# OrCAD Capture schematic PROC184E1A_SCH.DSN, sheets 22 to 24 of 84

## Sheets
22 22. SOC DEBUG: size C; title: DEBUG; note: PROC184_SCH
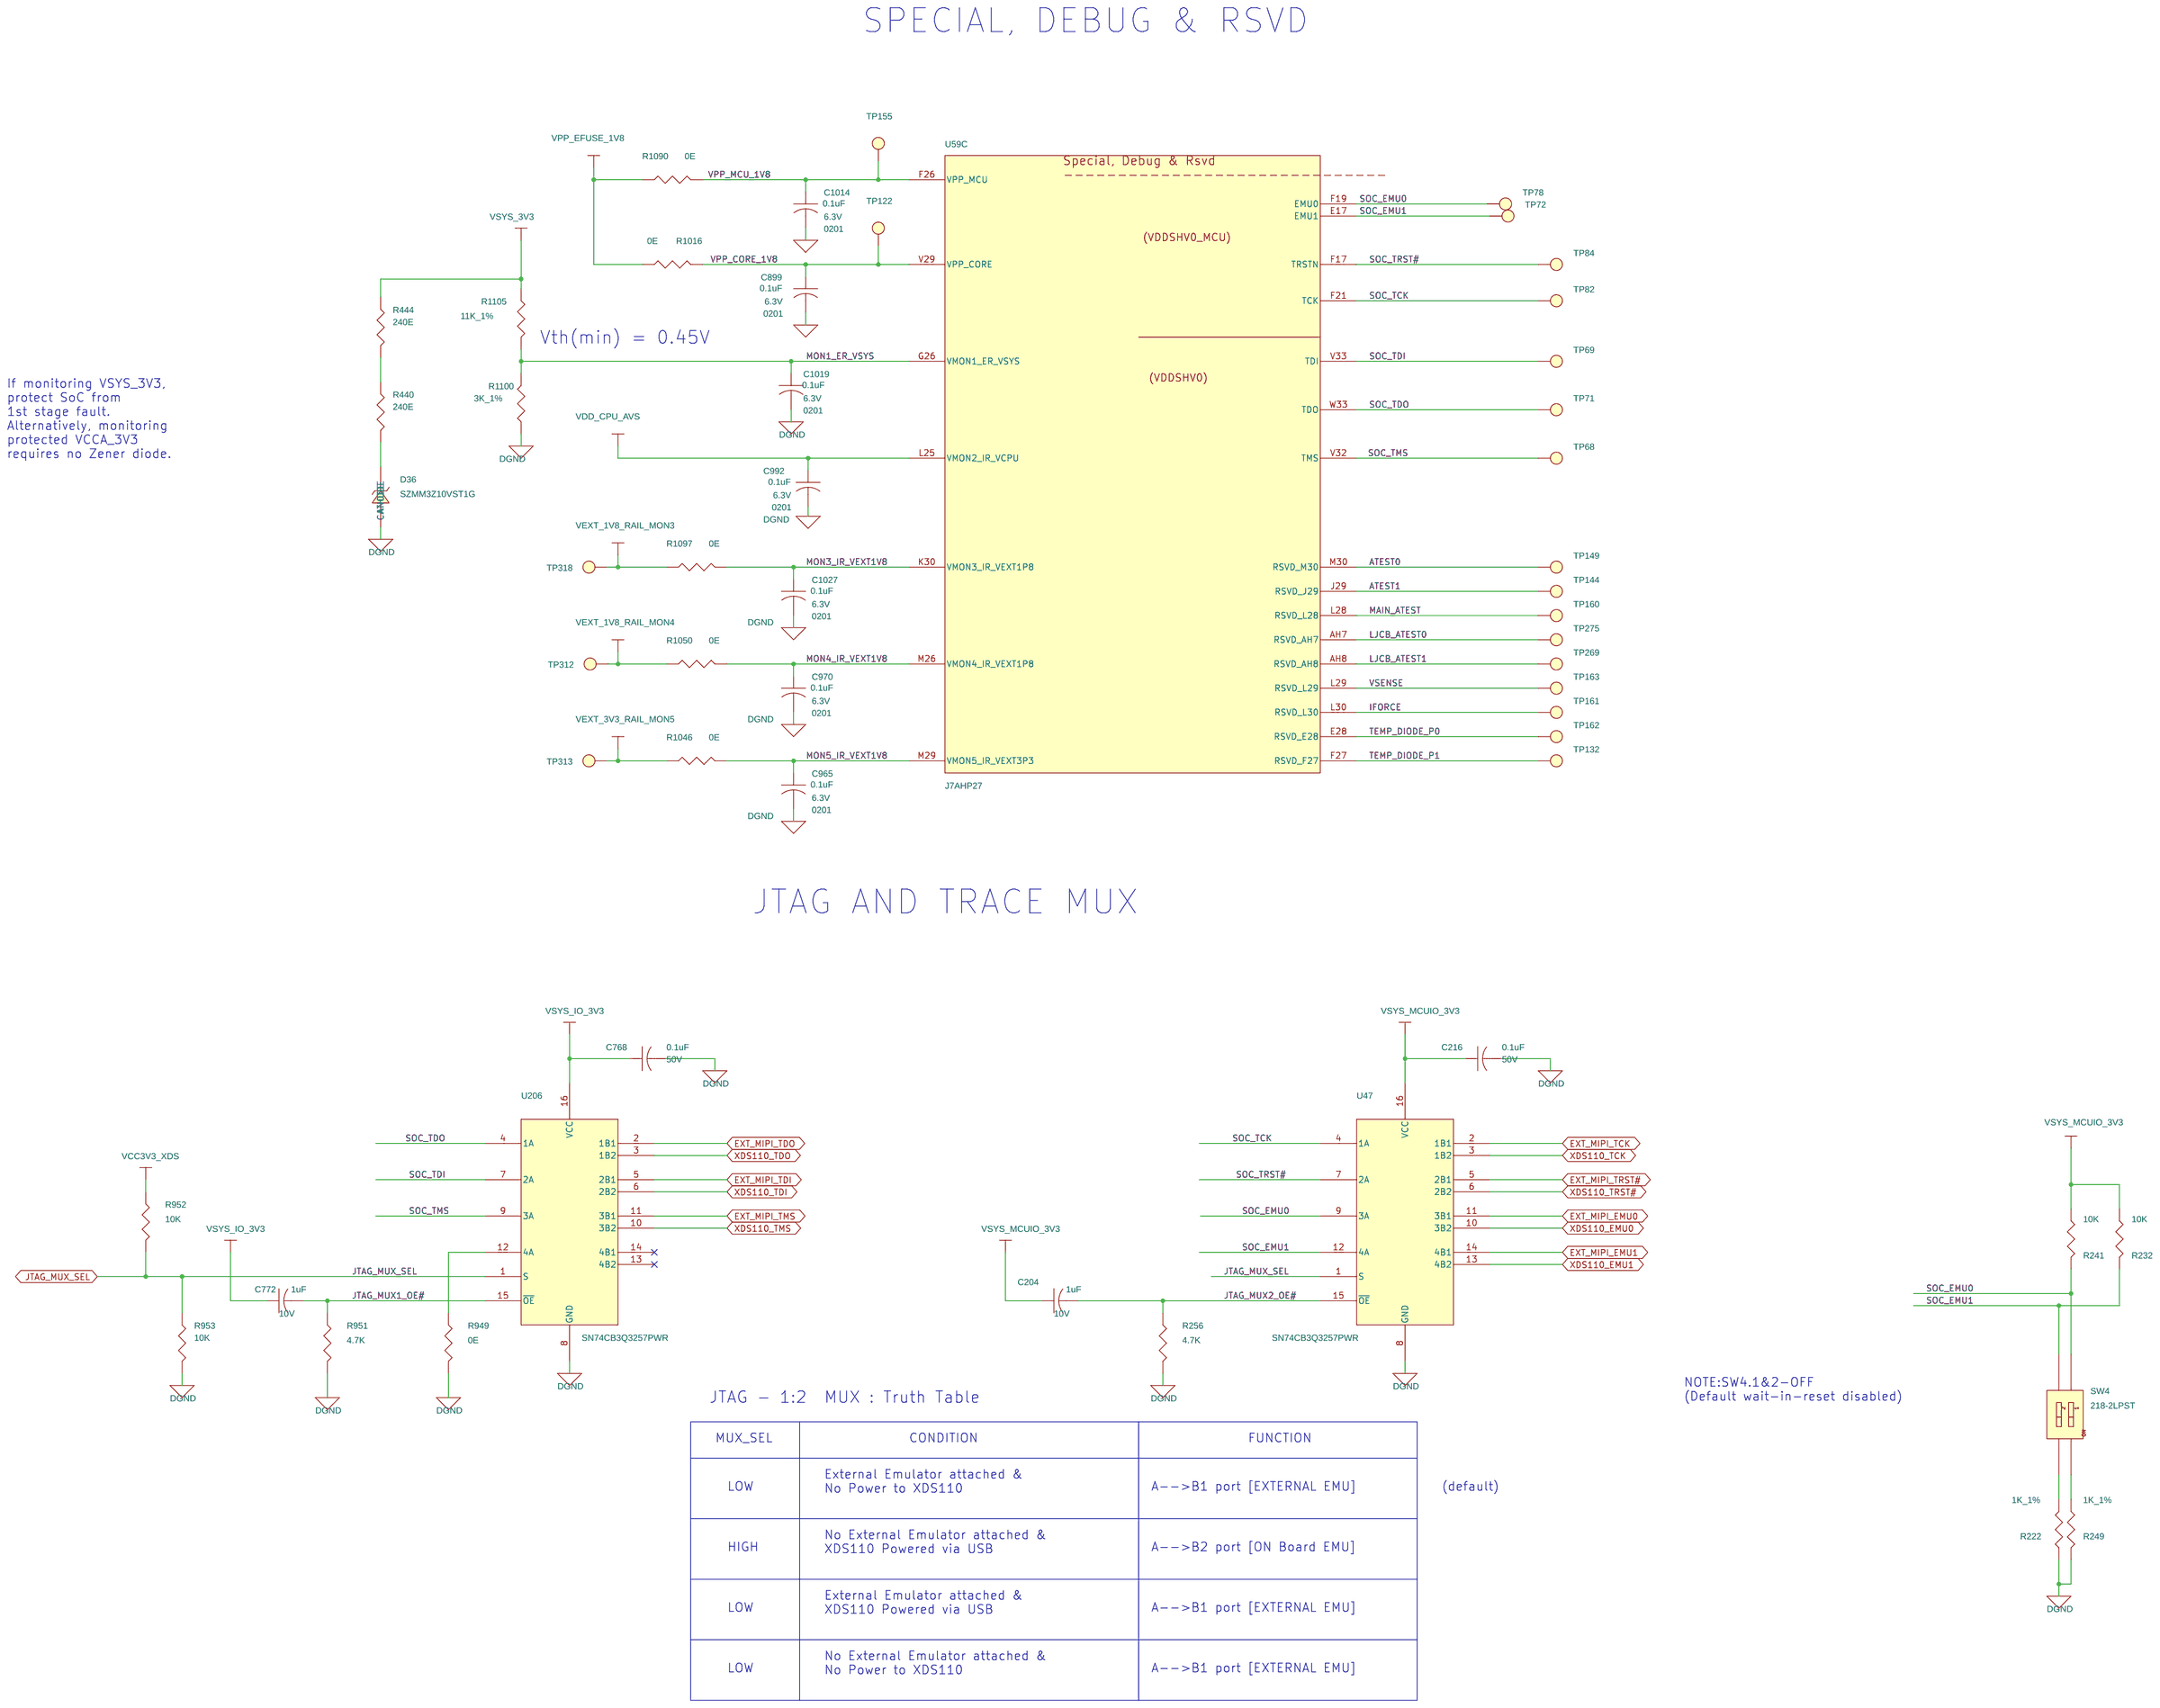
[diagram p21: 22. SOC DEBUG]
23 76.PMIC SUPPORT CRT: size C; title: PMIC SUPPORT CIRCUITRY; note: PROC184_SCH
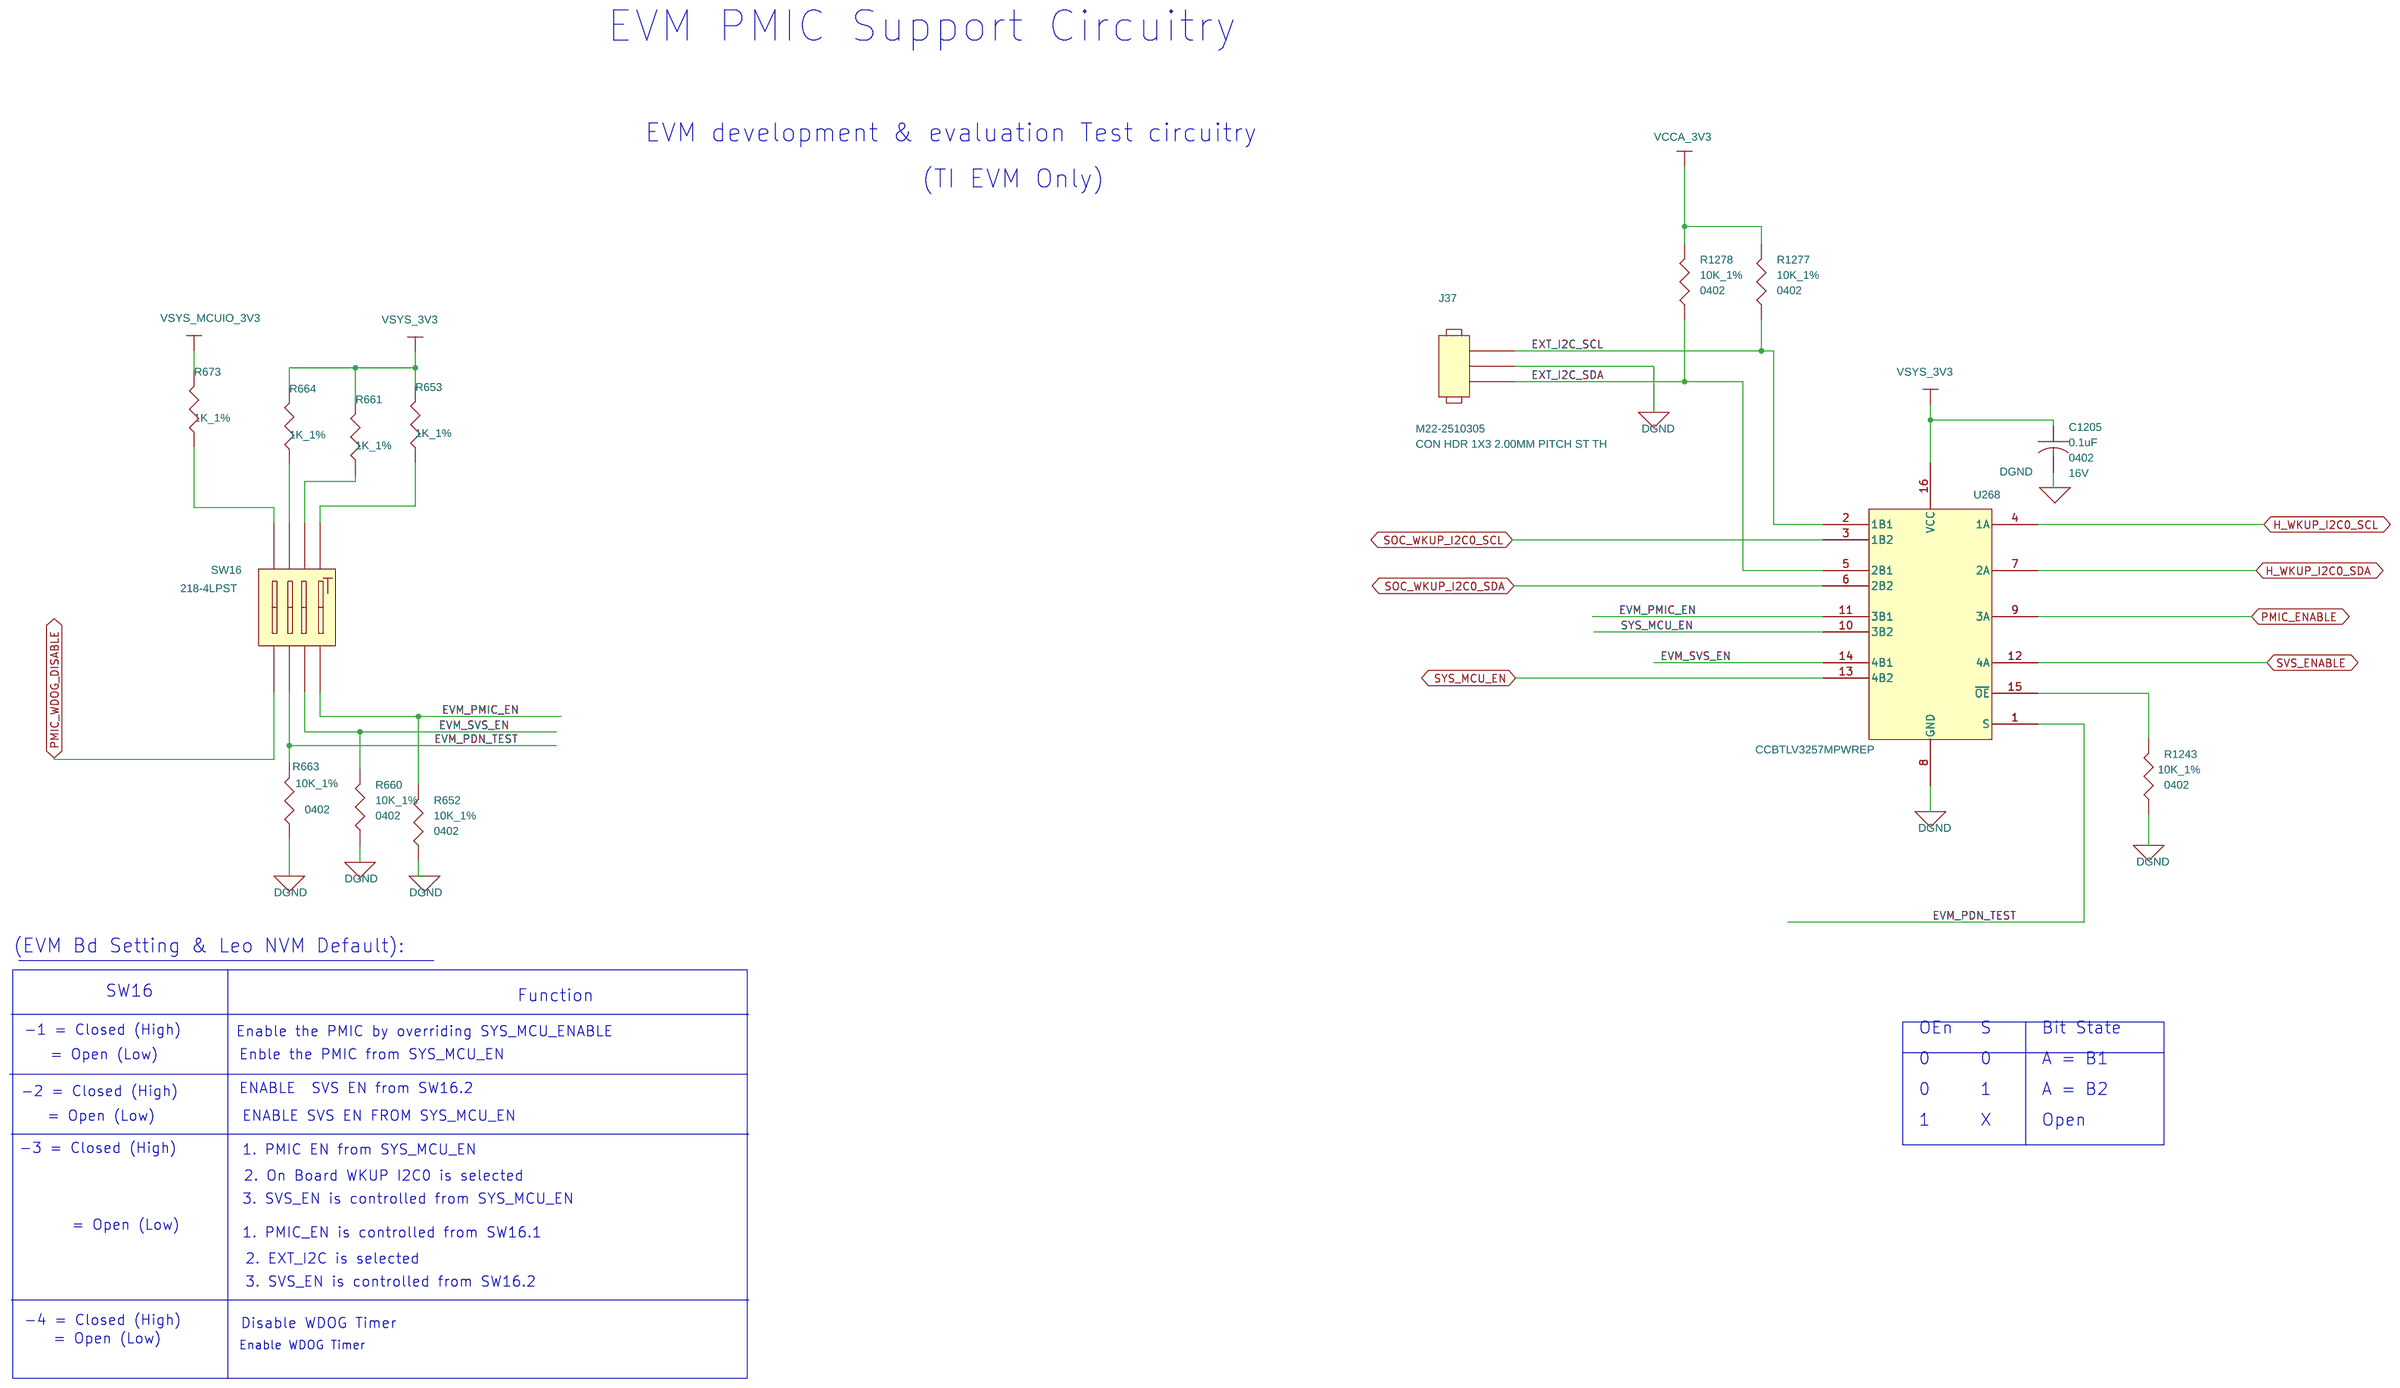
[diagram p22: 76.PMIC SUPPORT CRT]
24 23. SOC USB2.0: size C; title: SOC USB 2.0; company: TEXAS INSTRUMENTS INCORPORATED; note: PROC184_SCH
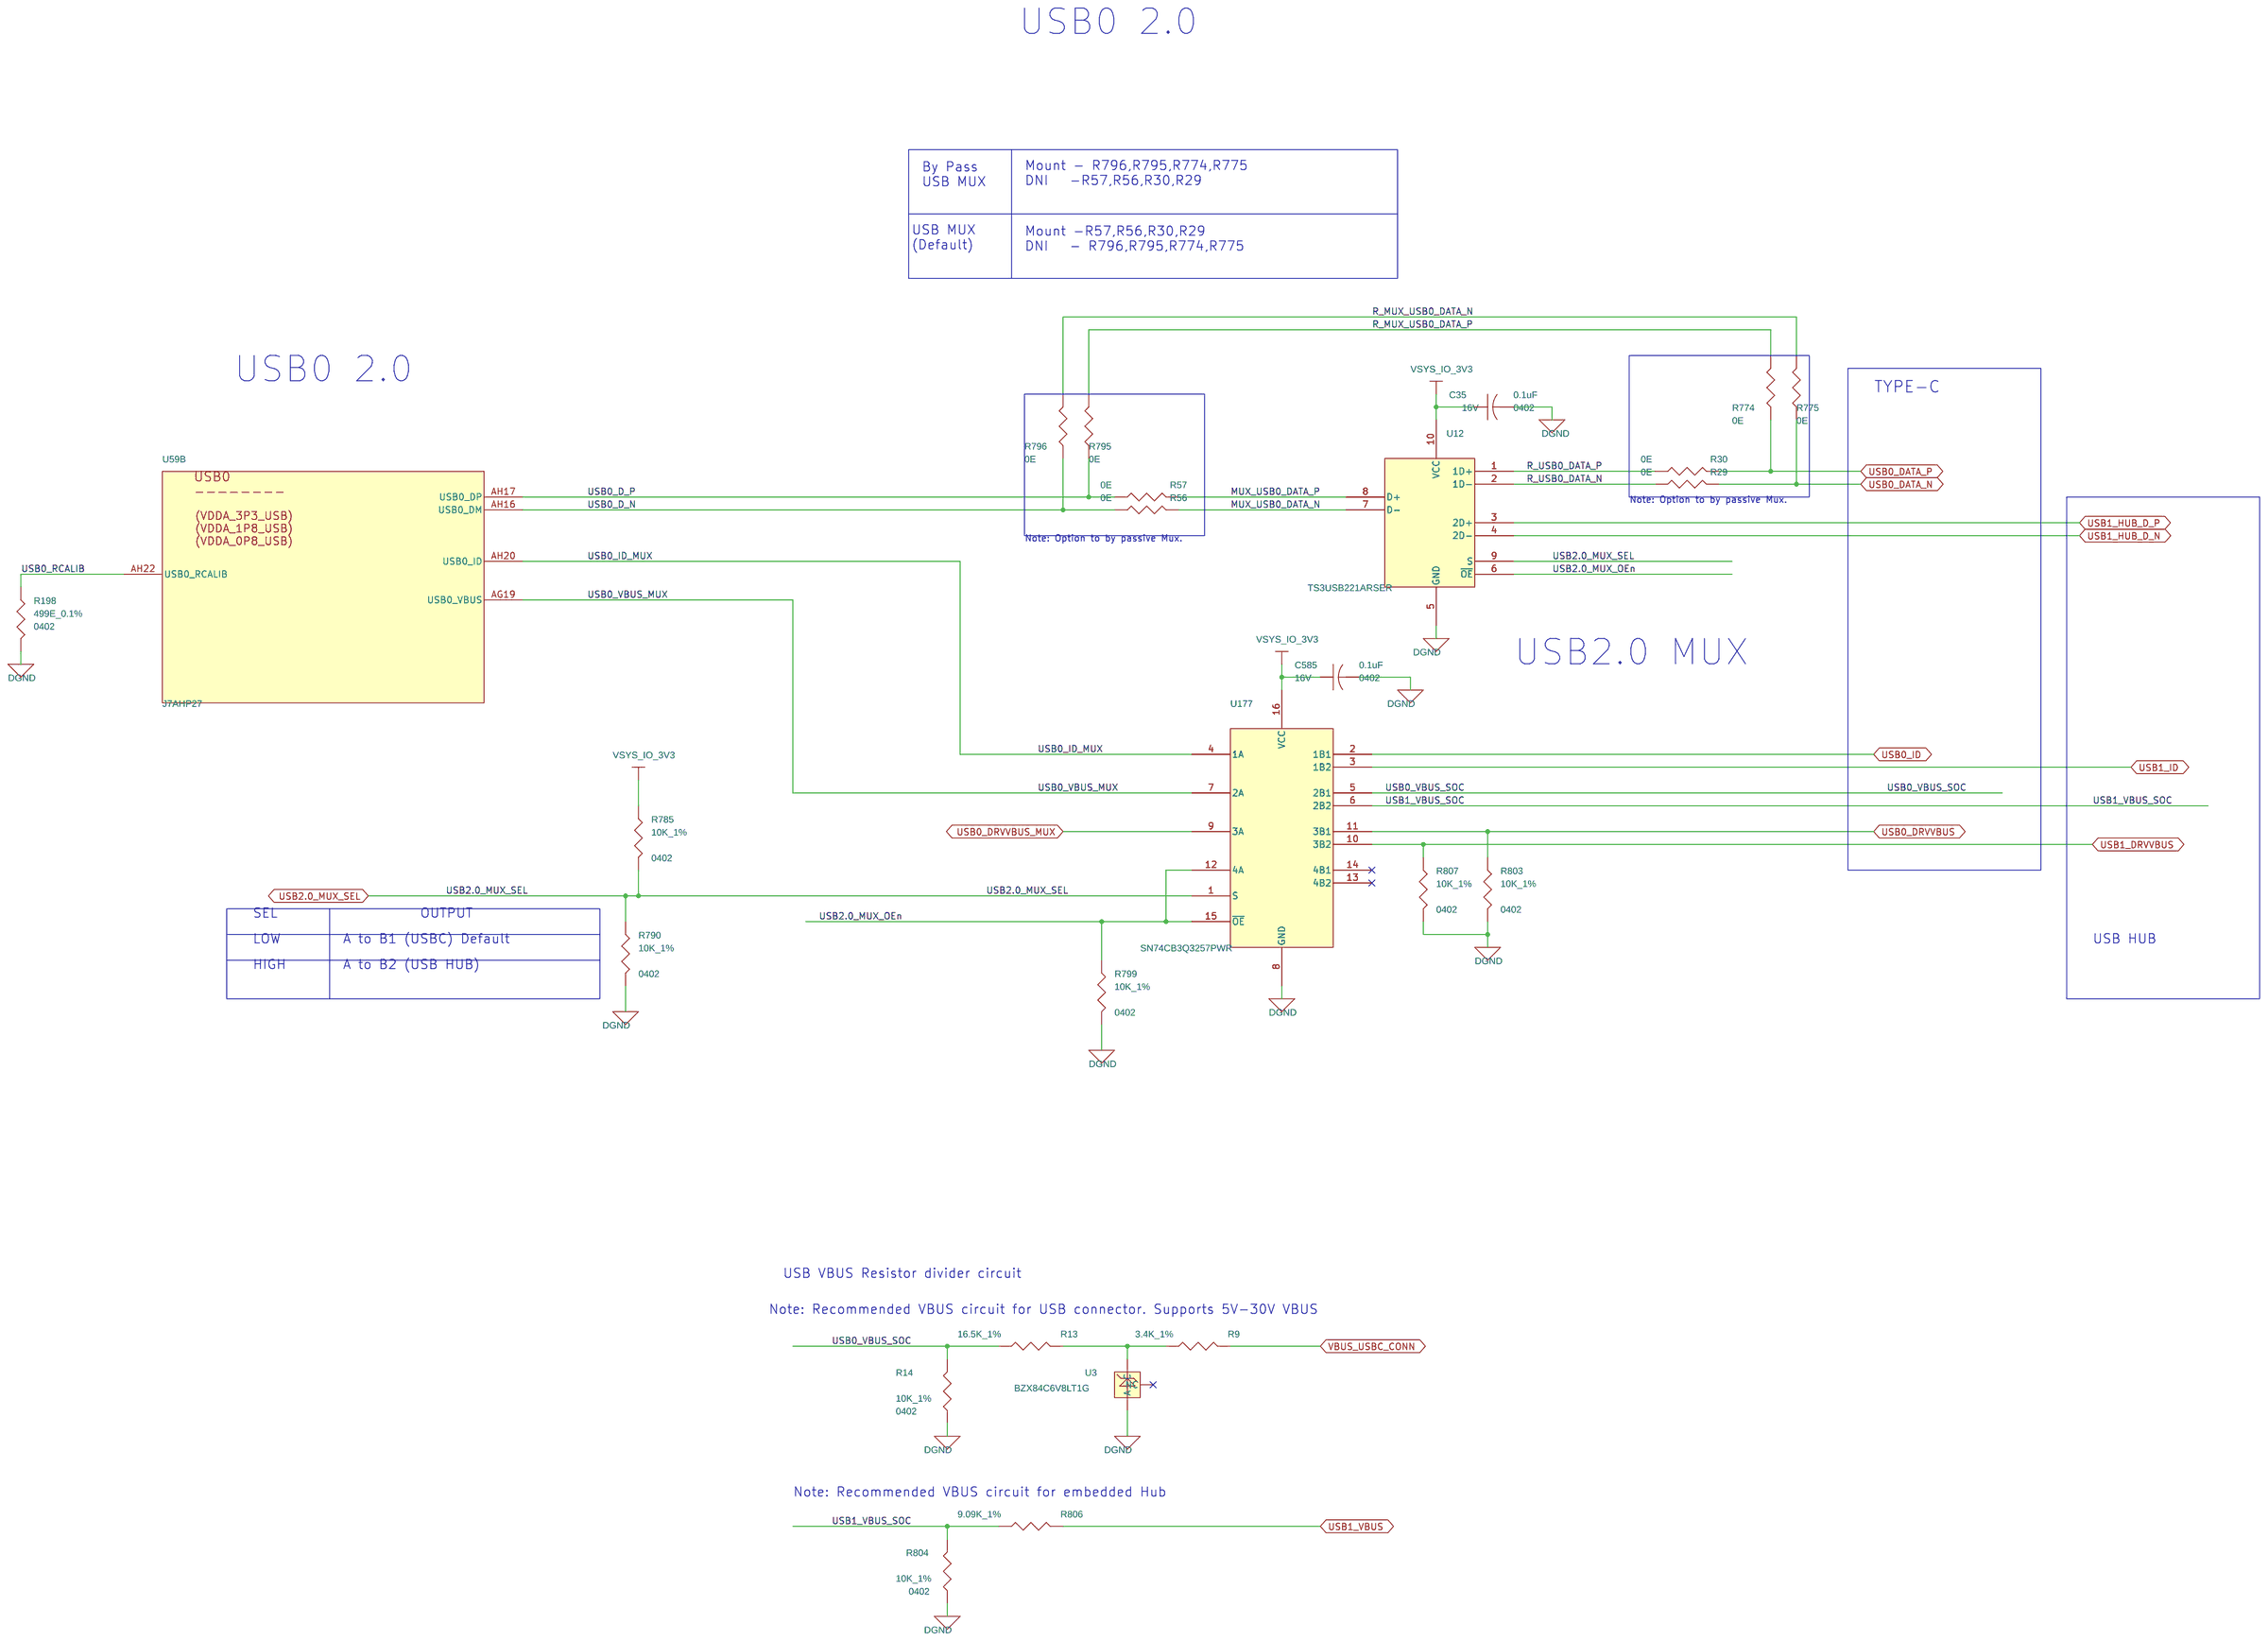
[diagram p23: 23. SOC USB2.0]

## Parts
sheet 15. SOC EMIF1 & LPDDR4
U59  J7AHP27  [BGASKT-33X33-1063-P8MM]  (sections A,B,C,D,E,F,G,H,I,J,K,L,M,N,O,P,Q,R,S,T,U,V,W)
sheet 22. SOC DEBUG
C204  1uF  [CAP0402_0-75]
C216  0.1uF  [CAP0402_0-75]
C768  0.1uF  [CAP0402_0-75]
C772  1uF  [CAP0402_0-75]
C899  0.1uF  [CAP0201_0-5]
C965  0.1uF  [CAP0201_0-5]
C970  0.1uF  [CAP0201_0-5]
C992  0.1uF  [CAP0201_0-5]
C1014  0.1uF  [CAP0201_0-5]
C1019  0.1uF  [CAP0201_0-5]
C1027  0.1uF  [CAP0201_0-5]
D36  SZMM3Z10VST1G  [DIO_SOD323_1-1]
R222  1K_1%  [RES0402_0-5]
R232  10K  [RES0402_0-5]
R241  10K  [RES0402_0-5]
R249  1K_1%  [RES0402_0-5]
R256  4.7K  [RES0402_0-5]
R440  240E  [RES0402_0-5]
R444  240E  [RES0402_0-5]
R949  0E  [RES0402_0-5]
R951  4.7K  [RES0402_0-5]
R952  10K  [RES0402_0-5]
R953  10K  [RES0402_0-5]
R1016  0E  [RES0603_0-75]
R1046  0E  [RES0603_0-75]
R1050  0E  [RES0603_0-75]
R1090  0E  [RES0603_0-75]
R1097  0E  [RES0603_0-75]
R1100  3K_1%  [RES0402_0-5]
R1105  11K_1%  [RES0402_0-5]
SW4  218-2LPST  [SW4_49-99_150X230_SMD_2-7]
TP68  TP30_SMD  [TP30_SMD]
TP69  TP30_SMD  [TP30_SMD]
TP71  TP30_SMD  [TP30_SMD]
TP72  TP30_SMD  [TP30_SMD]
TP78  TP30_SMD  [TP30_SMD]
TP82  TP30_SMD  [TP30_SMD]
TP84  TP30_SMD  [TP30_SMD]
TP122  TP30_SMD  [TP30_SMD]
TP132  TP30_SMD  [TP30_SMD]
TP144  TP30_SMD  [TP30_SMD]
TP149  TP30_SMD  [TP30_SMD]
TP155  TP30_SMD  [TP30_SMD]
TP160  TP30_SMD  [TP30_SMD]
TP161  TP30_SMD  [TP30_SMD]
TP162  TP30_SMD  [TP30_SMD]
TP163  TP30_SMD  [TP30_SMD]
TP269  TP30_SMD  [TP30_SMD]
TP275  TP30_SMD  [TP30_SMD]
TP312  TP30_SMD  [TP30_SMD]
TP313  TP30_SMD  [TP30_SMD]
TP318  TP30_SMD  [TP30_SMD]
U47  SN74CB3Q3257PWR  [TSSOP16_25-59_205X180]
U206  SN74CB3Q3257PWR  [TSSOP16_25-59_205X180]
sheet 23. SOC USB2.0
C35  0.1uF  [CAP0402_0-75]
C585  0.1uF  [CAP0402_0-75]
R9  3.4K_1%  [RES0402_0-5]
R13  16.5K_1%  [RES0402_0-5]
R14  10K_1%  [RES0402_0-5]
R29  0E  [RES0402_0-5]
R30  0E  [RES0402_0-5]
R56  0E  [RES0402_0-5]
R57  0E  [RES0402_0-5]
R198  499E_0.1%  [RES0402_0-5]
R774  0E  [RES0402_0-5]
R775  0E  [RES0402_0-5]
R785  10K_1%  [RES0402_0-5]
R790  10K_1%  [RES0402_0-5]
R795  0E  [RES0402_0-5]
R796  0E  [RES0402_0-5]
R799  10K_1%  [RES0402_0-5]
R803  10K_1%  [RES0402_0-5]
R804  10K_1%  [RES0402_0-5]
R806  9.09K_1%  [RES0402_0-5]
R807  10K_1%  [RES0402_0-5]
U3  BZX84C6V8LT1G  [SOT23-123_1-2]
U12  TS3USB221ARSER  [UQFN10_19-68_80X60]
U177  SN74CB3Q3257PWR  [TSSOP16_25-59_205X180]
sheet 76.PMIC SUPPORT CRT
C1205  0.1uF  [CAP0402_0-75]
J37  HDR_1X3  [HDR_1X3_78-74_S_T]
R652  10K_1%  [RES0402_0-5]
R653  1K_1%  [RES0402_0-5]
R660  10K_1%  [RES0402_0-5]
R661  1K_1%  [RES0402_0-5]
R663  10K_1%  [RES0402_0-5]
R664  1K_1%  [RES0402_0-5]
R673  1K_1%  [RES0402_0-5]
R1243  10K_1%  [RES0402_0-5]
R1277  10K_1%  [RES0402_0-5]
R1278  10K_1%  [RES0402_0-5]
SW16  218-4LPST  [SW8_218-4LPS_230X250_SMD_2-7]
U268  CCBTLV3257MPWREP  [TSSOP16_25-59_205X180_1-2]

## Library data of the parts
U59 = J7AHP27SoC_BGA1063: IC J7AHP27 SoC EVM MICROPROCESSOR BGA1063; Chkd/date: PRADEEP/181223; Crtd /date: TAMILARASU/111223; Custom_Duty: 15%; Customs_HS_Code: 85423100; Distributor_name: NA; Distributor_part_number: NA; Footprint Path: Y:\MIS_DATABASE\Library\ALTIUM_TOOL\PCB_FOOTPRINTS\Altium_Footprint_Lib.PcbLib; Height: 3.30MM; Library Path: Y:\MIS_DATABASE\Library\ALTIUM_TOOL\SCHEMATICS_PARTS\MS_MICROPROCESSOR_Library.schlib; Mfr_name: NA; Mistral Part No: 141223120002; Package: BGA1063; Part_type: ICS\DIGITAL\MICROPROCESSOR; Project: J7AHP27_V08 SOC; RoHS: NA; Temperature: NA; Tolerance: NA; Voltage: NA; Wattage: NA; Weight: NA; Datasheet: Y:\MIS_DATABASE\DATASHEETS\ICS\DIGITAL\MICROCONTROLLER\J7AHP27.PDF
C204 C772 = CAP: CAP CERAMIC 1uF 10V 10% X7S AUTO 0402; Automotive Alternate_mfr_name: TAIYO YUDEN; Automotive Alternate_mfr_part_number: EMK105BJ105KVHF; Chkd/date: MANIRAJA/100918; Crtd /date: ALVY/100918; Custom_Duty: 15%; Customs_HS_Code: 85322990; Direct Alternate_mfr_name: YAGEO AMERICA; Direct Alternate_mfr_part_number: CC0402KRX5R7BB105; Distributor_name: DIGIKEY; Distributor_part_number: 490-13409-1-ND; Footprint Path: Y:\MIS_DATABASE\Library\ALTIUM_TOOL\PCB_FOOTPRINTS\Altium_Footprint_Lib.PcbLib; Height: 0.70MM; Library Path: Y:\MIS_DATABASE\Library\ALTIUM_TOOL\SCHEMATICS_PARTS\MS_DISCRETE_Library.schlib; Manufacturer: TDK CORPORATION; Mfr_name: MURATA; Mfr_part_number: GCM155C71A105KE38D; Mistral Part No: 120018090021-R; Package: 0402; Part_type: CAPACITORS\CERAMIC; Project: SMART-M_SCRIPTALK_PB; RoHS: RoHS; Temperature: -55°C+125°C; Tolerance: 10%; Voltage: 10V; Wattage: NA; Weight: 6mg; Datasheet: Y:\MIS_DATABASE\DATASHEETS\CAPACITORS\MURATA-GCM-SER.PDF
C216 C768 = CAP: CAP CERAMIC 0.1uF 50V 10% X7R 0402; Automotive Alternate_mfr_name: TDK; Automotive Alternate_mfr_part_number: CGA2B3X7R1H104K050BB; Chkd/date: MANIRAJA/261020; Crtd /date: ALVY/211020; Custom_Duty: 15%; Customs_HS_Code: 85322990; Direct Alternate_mfr_name: TDK; Direct Alternate_mfr_part_number: C1005X7R1H104K050BE; Distributor_name: DIGIKEY; Distributor_part_number: 490-10700-1-ND; Footprint Path: Y:\MIS_DATABASE\Library\ALTIUM_TOOL\PCB_FOOTPRINTS\Altium_Footprint_Lib.PcbLib; Height: 0.55MM; Library Path: Y:\MIS_DATABASE\Library\ALTIUM_TOOL\SCHEMATICS_PARTS\MS_DISCRETE_Library.schlib; Manufacturer: MURATA; Mfr_name: MURATA; Mfr_part_number: GRM155R71H104KE14D; Mistral Part No: 120011100014-R; Package: 0402; Part_type: CAPACITORS\CERAMIC; Project: J7_CP; RoHS: RoHS; Temperature: -55°C+125°C; Tolerance: 10%; Voltage: 50V; Wattage: NA; Weight: 3.1mg; Datasheet: Y:\MIS_DATABASE\DATASHEETS\CAPACITORS\GRM155R71H104KE14.PDF
C899 C965 C970 C1014 C1019 C1027 = CAP: CAP CERAMIC 0.1uF 6.3V 10% X7S AUTO 0201; Chkd/date: MANIRAJA/011018; Crtd /date: MANIRAJA/011018; Custom_Duty: 15%; Customs_HS_Code: 85322990; Distributor_name: NA; Distributor_part_number: NA; Footprint Path: Y:\MIS_DATABASE\Library\ALTIUM_TOOL\PCB_FOOTPRINTS\Altium_Footprint_Lib.PcbLib; Height: 0.33MM; Library Path: Y:\MIS_DATABASE\Library\ALTIUM_TOOL\SCHEMATICS_PARTS\MS_DISCRETE_Library.schlib; Manufacturer: MURATA; Mfr_name: MURATA; Mfr_part_number: GCM033C70J104KE02D; Mistral Part No: 120018100001-R; Package: 0201; Part_type: CAPACITORS\CERAMIC; Project: TI_J7_SVB-DUT; RoHS: RoHS; Temperature: -55°C+125°C; Tolerance: 10%; Voltage: 6.3V; Wattage: NA; Weight: NA; Datasheet: Y:\MIS_DATABASE\DATASHEETS\CAPACITORS\MURATA-GCM-SER.PDF
C992 = CAP: CAP CERAMIC 0.1uF 6.3V 10% X7S AUTO 0201; Assembly_Instruction: DNI; Chkd/date: MANIRAJA/011018; Crtd /date: MANIRAJA/011018; Custom_Duty: 15%; Customs_HS_Code: 85322990; Distributor_name: NA; Distributor_part_number: NA; Footprint Path: Y:\MIS_DATABASE\Library\ALTIUM_TOOL\PCB_FOOTPRINTS\Altium_Footprint_Lib.PcbLib; Height: 0.33MM; Library Path: Y:\MIS_DATABASE\Library\ALTIUM_TOOL\SCHEMATICS_PARTS\MS_DISCRETE_Library.schlib; Manufacturer: MURATA; Mfr_name: MURATA; Mfr_part_number: GCM033C70J104KE02D; Mistral Part No: 120018100001-R; Package: 0201; Part_type: CAPACITORS\CERAMIC; Project: TI_J7_SVB-DUT; RoHS: RoHS; Temperature: -55°C+125°C; Tolerance: 10%; Voltage: 6.3V; Wattage: NA; Weight: NA; Datasheet: Y:\MIS_DATABASE\DATASHEETS\CAPACITORS\MURATA-GCM-SER.PDF
D36 = DIODE_ZENER: DIODE ZENER 10V 300mW SOD323; Chkd/date: MANIRAJA/170419; Crtd /date: MANIRAJA/170419; Custom_Duty: 15%; Customs_HS_Code: 85412900; Distributor_name: DIGIKEY; Distributor_part_number: SZMM3Z10VST1GOSCT-ND; Footprint Path: Y:\MIS_DATABASE\Library\ALTIUM_TOOL\PCB_FOOTPRINTS\Altium_Footprint_Lib.PcbLib; Height: 1.10MM; Library Path: Y:\MIS_DATABASE\Library\ALTIUM_TOOL\SCHEMATICS_PARTS\MS_DISCRETE_Library.schlib; Manufacturer: ON SEMICONDUCTOR; Mfr_name: ON SEMICONDUCTOR; Mistral Part No: 130019040011-R; Package: SOD323; Part_type: DIODE\ZENER; Project: J7ES_SOM_DUAL-LEO_PMIC; RoHS: RoHS; Temperature: -65°C+150°C; Tolerance: NA; Voltage: 10V; Wattage: NA; Weight: NA; Datasheet: Y:\MIS_DATABASE\DATASHEETS\DISCRETES\DIODES\SZMM3ZXXXST1G.PDF
R222 R249 R653 R661 R664 R673 = RESISTOR: RES 1K 1/10W 1% 0402; Chkd/date: VASANTHA/281216; Crtd /date: MAZHAR/150506; Custom_Duty: 15%; Customs_HS_Code: 85332119; Distributor_name: DIGIKEY; Distributor_part_number: P1.00KLCT-ND; Footprint Path: Y:\MIS_DATABASE\Library\ALTIUM_TOOL\PCB_FOOTPRINTS\Altium_Footprint_Lib.PcbLib; Height: 0.40MM; Library Path: Y:\MIS_DATABASE\Library\ALTIUM_TOOL\SCHEMATICS_PARTS\MS_DISCRETE_Library.schlib; Manufacturer: PANASONIC-ECG; Mfr_name: PANASONIC-ECG; Mfr_part_number: ERJ-2RKF1001X; Mistral Part No: 110009030411-R; Package: 0402; Part_type: RESISTORS\FIXED; Project: VOCERA; RoHS: RoHS; Temperature: -55°C+155°C; Tolerance: 1%; Voltage: NA; Wattage: 1/10W; Weight: 0.8mg; Datasheet: Y:\MIS_DATABASE\DATASHEETS\RESISTORS\PAN-ERJSER_NOV17.PDF
R232 R241 R952 = RESISTOR: RES 10K 1/16W 5% 0402; Chkd/date: VASANTHA/061216; Crtd /date: MAZHAR/230805; Custom_Duty: 15%; Customs_HS_Code: 85332119; Distributor_name: DIGIKEY; Distributor_part_number: 311-10KJRCT-ND; Footprint Path: Y:\MIS_DATABASE\Library\ALTIUM_TOOL\PCB_FOOTPRINTS\Altium_Footprint_Lib.PcbLib; Height: 0.40MM; Library Path: Y:\MIS_DATABASE\Library\ALTIUM_TOOL\SCHEMATICS_PARTS\MS_DISCRETE_Library.schlib; Manufacturer: YAGEO AMERICA; Mfr_name: YAGEO AMERICA; Mfr_part_number: RC0402JR-0710KL; Mistral Part No: 110011060021-R; Package: 0402; Part_type: RESISTORS\FIXED; Project: HSE; RoHS: RoHS; Temperature: -55°C+155°C; Tolerance: 5%; Voltage: NA; Wattage: 1/16W; Weight: 0.65mg; Datasheet: Y:\MIS_DATABASE\DATASHEETS\RESISTORS\RCXXXXL-SER_MAR18.PDF
R256 R951 = RESISTOR: RES 4.7K 1/16W 5% 0402; Chkd/date: VASANTHA/130516; Crtd /date: VASANTHA/130516; Custom_Duty: 15%; Customs_HS_Code: 85332119; Distributor_name: DIGIKEY; Distributor_part_number: 311-4.7KJRCT-ND; Footprint Path: Y:\MIS_DATABASE\Library\ALTIUM_TOOL\PCB_FOOTPRINTS\Altium_Footprint_Lib.PcbLib; Height: 0.40MM; Library Path: Y:\MIS_DATABASE\Library\ALTIUM_TOOL\SCHEMATICS_PARTS\MS_DISCRETE_Library.schlib; Manufacturer: YAGEO AMERICA; Mfr_name: YAGEO AMERICA; Mfr_part_number: RC0402JR-074K7L; Mistral Part No: 110011060001-R; Package: 0402; Part_type: RESISTORS\FIXED; Project: TMDXCSK368; RoHS: RoHS; Temperature: -55°C+155°C; Tolerance: 5%; Voltage: NA; Wattage: 1/16W; Weight: 0.65mg; Datasheet: Y:\MIS_DATABASE\DATASHEETS\RESISTORS\RCXXXXL-SER_MAR18.PDF
R440 R444 = RESISTOR: RES 240E 1/16W 5% 0402; Chkd/date: VASANTHA/060117; Crtd /date: GEETHA/070606; Custom_Duty: 15%; Customs_HS_Code: 85332119; Distributor_name: DIGIKEY; Distributor_part_number: 311-240JRCT-ND; Footprint Path: Y:\MIS_DATABASE\Library\ALTIUM_TOOL\PCB_FOOTPRINTS\Altium_Footprint_Lib.PcbLib; Height: 0.40MM; Library Path: Y:\MIS_DATABASE\Library\ALTIUM_TOOL\SCHEMATICS_PARTS\MS_DISCRETE_Library.schlib; Manufacturer: YAGEO AMERICA; Mfr_name: YAGEO AMERICA; Mfr_part_number: RC0402JR-07240RL; Mistral Part No: 110009030544-R; Package: 0402; Part_type: RESISTORS\FIXED; Project: VOCERA; RoHS: RoHS; Temperature: -55°C+155°C; Tolerance: 5%; Voltage: NA; Wattage: 1/16W; Weight: 0.65mg; Datasheet: Y:\MIS_DATABASE\DATASHEETS\RESISTORS\RCXXXXL-SER_MAR18.PDF
R29 R30 R56 R57 R949 = RESISTOR: RES 0E 1/10W JUMPER 0402; Chkd/date: VASANTHA/061216; Crtd /date: NAVEED/201014; Custom_Duty: 15%; Customs_HS_Code: 85332119; Distributor_name: DIGIKEY; Distributor_part_number: P0.0JCT-ND; Footprint Path: Y:\MIS_DATABASE\Library\ALTIUM_TOOL\PCB_FOOTPRINTS\Altium_Footprint_Lib.PcbLib; Height: 0.40MM; IBISSP_MODLES: VALUE REPEATING 2 TIME; Library Path: Y:\MIS_DATABASE\Library\ALTIUM_TOOL\SCHEMATICS_PARTS\MS_DISCRETE_Library.schlib; Manufacturer: PANASONIC-ECG; Mfr_name: PANASONIC-ECG; Mfr_part_number: ERJ-2GE0R00X; Mistral Part No: 110018030052-R; Package: 0402; Part_type: RESISTORS\FIXED; Project: AEGIS POM; RoHS: RoHS; Temperature: -55°C+155°C; Tolerance: NA; Voltage: NA; Wattage: 1/10W; Weight: 0.8mg; Datasheet: Y:\MIS_DATABASE\DATASHEETS\RESISTORS\PAN-ERJSER_NOV17.PDF
R953 = RESISTOR: RES 10K 1/16W 5% 0402; Assembly_Instruction: DNI; Chkd/date: VASANTHA/061216; Crtd /date: MAZHAR/230805; Custom_Duty: 15%; Customs_HS_Code: 85332119; Distributor_name: DIGIKEY; Distributor_part_number: 311-10KJRCT-ND; Footprint Path: Y:\MIS_DATABASE\Library\ALTIUM_TOOL\PCB_FOOTPRINTS\Altium_Footprint_Lib.PcbLib; Height: 0.40MM; Library Path: Y:\MIS_DATABASE\Library\ALTIUM_TOOL\SCHEMATICS_PARTS\MS_DISCRETE_Library.schlib; Manufacturer: YAGEO AMERICA; Mfr_name: YAGEO AMERICA; Mfr_part_number: RC0402JR-0710KL; Mistral Part No: 110011060021-R; Package: 0402; Part_type: RESISTORS\FIXED; Project: HSE; RoHS: RoHS; Temperature: -55°C+155°C; Tolerance: 5%; Voltage: NA; Wattage: 1/16W; Weight: 0.65mg; Datasheet: Y:\MIS_DATABASE\DATASHEETS\RESISTORS\RCXXXXL-SER_MAR18.PDF
R1016 R1046 R1050 R1090 R1097 = RESISTOR: RES 0E 1/4W JUMPER 0603 (HP); Chkd/date: USMAN/170112; Crtd /date: CHAITHANYA/170112; Custom_Duty: 15%; Customs_HS_Code: 85332119; Distributor_name: DIGIKEY; Distributor_part_number: 541-0.0SBCT-ND; Footprint Path: Y:\MIS_DATABASE\Library\ALTIUM_TOOL\PCB_FOOTPRINTS\Altium_Footprint_Lib.PcbLib; Height: 0.55MM; Library Path: Y:\MIS_DATABASE\Library\ALTIUM_TOOL\SCHEMATICS_PARTS\MS_DISCRETE_Library.schlib; Manufacturer: VISHAY; Mfr_name: VISHAY; Mfr_part_number: CRCW06030000Z0EAHP; Mistral Part No: 110012010013-R; Package: 0603; Part_type: RESISTORS\FIXED; Project: NA10NG; Remarks: This part is pulse proof, high power; RoHS: RoHS; Temperature: -55°C+155°C; Tolerance: NA; Voltage: NA; Wattage: 1/4 W; Weight: 2mg; Datasheet: Y:\MIS_DATABASE\DATASHEETS\RESISTORS\CRCWXXX-HP_SEP16.PDF
R1100 = RESISTOR: RES 3K 1/16W 1% 0402; Chkd/date: MANIRAJA/101117; Crtd /date: MANIRAJA/101117; Custom_Duty: 15%; Customs_HS_Code: 85332119; Distributor_name: DIGIKEY; Distributor_part_number: 311-3KLRCT-ND; Footprint Path: Y:\MIS_DATABASE\Library\ALTIUM_TOOL\PCB_FOOTPRINTS\Altium_Footprint_Lib.PcbLib; Height: 0.40MM; Library Path: Y:\MIS_DATABASE\Library\ALTIUM_TOOL\SCHEMATICS_PARTS\MS_DISCRETE_Library.schlib; Manufacturer: YAGEO AMERICA; Mfr_name: YAGEO AMERICA; Mfr_part_number: RC0402FR-073KL; Mistral Part No: 110017110004-R; Package: 0402; Part_type: RESISTORS\FIXED; Project: TI_SVB_MAXWELL_DUT; RoHS: RoHS; Temperature: -55°C+155°C; Tolerance: 1%; Voltage: NA; Wattage: 1/16W; Weight: 0.65mg; Datasheet: Y:\MIS_DATABASE\DATASHEETS\RESISTORS\RCXXXXL-SER_MAR18.PDF
R1105 = RESISTOR: RES 11K 1/16W 1% 0402; Chkd/date: VASANTHA/251115; Crtd /date: VASANTHA/251115; Custom_Duty: 15%; Customs_HS_Code: 85332119; Distributor_name: DIGIKEY; Distributor_part_number: 311-11.0KLRCT-ND; Footprint Path: Y:\MIS_DATABASE\Library\ALTIUM_TOOL\PCB_FOOTPRINTS\Altium_Footprint_Lib.PcbLib; Height: 0.40MM; Library Path: Y:\MIS_DATABASE\Library\ALTIUM_TOOL\SCHEMATICS_PARTS\MS_DISCRETE_Library.schlib; Manufacturer: YAGEO AMERICA; Mfr_name: YAGEO AMERICA; Mfr_part_number: RC0402FR-0711KL; Mistral Part No: 110015110012-R; Package: 0402; Part_type: RESISTORS\FIXED; Project: TI_VLAN_SWITCH; RoHS: RoHS; Temperature: -55°C+155°C; Tolerance: 1%; Voltage: NA; Wattage: 1/16W; Weight: 0.65mg; Datasheet: Y:\MIS_DATABASE\DATASHEETS\RESISTORS\RCXXXXL-SER_MAR18.PDF
SW4 = SW4_GDH02S04: SWITCH DIP SPST HALF PITCH 2POS SMD; Chkd/date: VASANTHA/080715; Crtd /date: VASANTHA/241221; Custom_Duty: 24%; Customs_HS_Code: 85369090; Distributor_name: DIGIKEY; Distributor_part_number: CT2182LPST-ND; Height: 2.65MM; Manufacturer: CTS; Mfr_name: CTS; Mistral Part No: 130014120040-R; Package: SMD; Part_type: ELECTRO-MECHANICAL\SWITCH; Project: FREE SCALE POM; RoHS: RoHS; Temperature: -55°C+85°C; Tolerance: NA; Voltage: NA; Wattage: NA; Weight: NA; Datasheet: Y:\MIS_DATABASE\DATASHEETS\MISC\SWITCHES\128-12LPST.PDF
TP68 TP69 TP71 TP72 TP78 TP82 TP84 TP132 TP144 TP149 TP160-TP163 TP269 TP275 TP312 TP313 TP318 = TESTPOINT: TESTPOINT CIR 30 SMD; ASSEMBLY: DNP; Chkd/date: SHREESHAIL/171006; Crtd /date: MAZHAR/171006; Custom_Duty: NA; Customs_HS_Code: NA; Distributor_name: NA; Distributor_part_number: NA; Footprint Path: Y:\MIS_DATABASE\Library\ALTIUM_TOOL\PCB_FOOTPRINTS\Altium_Footprint_Lib.PcbLib; Height: NA; Library Path: Y:\MIS_DATABASE\Library\ALTIUM_TOOL\SCHEMATICS_PARTS\MS_DISCRETE_Library.schlib; MANUFACTURER: LOCAL; MECHANICAL 3D STEP FILE: NA; Mfr_name: LOCAL; Mistral Part No: 130009030930; Package: SMD; Part #: SMT-TP030; Project: BT MODULE_CSRBC04; RoHS: NA; Temperature: NA; Tolerance: NA; Voltage: NA; Wattage: NA; Weight: NA; Datasheet: NA
TP122 TP155 = TESTPOINT: TESTPOINT CIR 30 SMD; Chkd/date: SHREESHAIL/171006; Crtd /date: MAZHAR/171006; Custom_Duty: NA; Customs_HS_Code: NA; Distributor_name: NA; Distributor_part_number: NA; Footprint Path: Y:\MIS_DATABASE\Library\ALTIUM_TOOL\PCB_FOOTPRINTS\Altium_Footprint_Lib.PcbLib; Height: NA; Library Path: Y:\MIS_DATABASE\Library\ALTIUM_TOOL\SCHEMATICS_PARTS\MS_DISCRETE_Library.schlib; MECHANICAL 3D STEP FILE: NA; Manufacturer: LOCAL; Mfr_name: LOCAL; Mistral Part No: 130009030930; Package: SMD; Project: BT MODULE_CSRBC04; RoHS: NA; Temperature: NA; Tolerance: NA; Voltage: NA; Wattage: NA; Weight: NA; Datasheet: NA
U47 U177 U206 = SN74CB3Q3257PWR_TSSOP16: IC 4BIT 1-OF-2 FET MULTIPLEXER/DEMULTIPLEXER TSSOP16; Chkd/date: SUHAS/251010; Crtd /date: USMAN/060109; Custom_Duty: 15%; Customs_HS_Code: 85423100; Distributor_name: DIGIKEY; Distributor_part_number: 296-19138-1-ND; Height: 1.20MM; Manufacturer: TEXAS INSTRUMENTS; Mfr_name: TEXAS INSTRUMENTS; Mistral Part No: 141009030117-R; Package: TSSOP16; Part_type: ICS\DIGITAL\COMBINATIONAL; Project: OMAP_EVM; RoHS: Sb/ Br FREE; Temperature: -40°C+85°C; Datasheet: Y:\MIS_DATABASE\DATASHEETS\ICS\DIGITAL\COMBINATIONAL\SN74CB3Q3257.PDF
C35 C585 C1205 = CAP: CAP CERAMIC 0.1uF 16V 10% X7R AUTO 0402; Automotive Alternate_mfr_name: TDK; Automotive Alternate_mfr_part_number: CGA2B1X7R1C104K050BC; Chkd/date: NAVEED/021014; Crtd /date: VASANTHA/300514; Custom_Duty: 15%; Customs_HS_Code: 85322990; Direct Alternate_mfr_name: MURATA; Direct Alternate_mfr_part_number: GCM155R71C104JA55D; Distributor_name: DIGIKEY; Distributor_part_number: 490-4759-1-ND; Footprint Path: Y:\MIS_DATABASE\Library\ALTIUM_TOOL\PCB_FOOTPRINTS\Altium_Footprint_Lib.PcbLib; Height: 0.55MM; Library Path: Y:\MIS_DATABASE\Library\ALTIUM_TOOL\SCHEMATICS_PARTS\MS_DISCRETE_Library.schlib; Manufacturer: MURATA; Mfr_name: MURATA; Mfr_part_number: GCM155R71C104KA55D; Mistral Part No: 120016070006-R; Package: 0402; Part_type: CAPACITORS\CERAMIC; Project: DCMIST_FPGA_CARD; RoHS: RoHS; Temperature: -55°C+125°C; Tolerance: 10%; Voltage: 16V; Wattage: NA; Weight: 6mg; Datasheet: Y:\MIS_DATABASE\DATASHEETS\CAPACITORS\MURATA-GCM-SER.PDF
R9 = RESISTOR: RES 3.4K 1/10W 1% 0402; Chkd/date: USMAN/231211; Crtd /date: CHAITHANYA/231211; Custom_Duty: 15%; Customs_HS_Code: 85332119; Distributor_name: DIGIKEY; Distributor_part_number: P3.40KLCT-ND; Footprint Path: Y:\MIS_DATABASE\Library\ALTIUM_TOOL\PCB_FOOTPRINTS\Altium_Footprint_Lib.PcbLib; Height: 0.40MM; Library Path: Y:\MIS_DATABASE\Library\ALTIUM_TOOL\SCHEMATICS_PARTS\MS_DISCRETE_Library.schlib; Manufacturer: PANASONIC-ECG; Mfr_name: PANASONIC-ECG; Mfr_part_number: ERJ-2RKF3401X; Mistral Part No: 110011120023-R; Package: 0402; Part_type: RESISTORS\FIXED; Project: NA10NG; RoHS: RoHS; Temperature: -55°C+155°C; Tolerance: 1%; Voltage: NA; Wattage: 1/10W; Weight: 0.8mg; Datasheet: Y:\MIS_DATABASE\DATASHEETS\RESISTORS\PAN-ERJSER_NOV17.PDF
R13 = RESISTOR: RES 16.5K 1/10W 1% 0402; Chkd/date: VASANTHA/291216; Crtd /date: MUDDU/080310; Custom_Duty: 15%; Customs_HS_Code: 85332119; Distributor_name: DIGIKEY; Distributor_part_number: P16.5KLCT-ND; Footprint Path: Y:\MIS_DATABASE\Library\ALTIUM_TOOL\PCB_FOOTPRINTS\Altium_Footprint_Lib.PcbLib; Height: 0.40MM; Library Path: Y:\MIS_DATABASE\Library\ALTIUM_TOOL\SCHEMATICS_PARTS\MS_DISCRETE_Library.schlib; Manufacturer: PANASONIC-ECG; Mfr_name: PANASONIC-ECG; Mfr_part_number: ERJ-2RKF1652X; Mistral Part No: 110010030024-R; Package: 0402; Part_type: RESISTORS\FIXED; Project: VME_DSP_SUITE; RoHS: RoHS; Temperature: -55°C+155°C; Tolerance: 1%; Voltage: NA; Wattage: 1/10W; Weight: 0.8mg; Datasheet: Y:\MIS_DATABASE\DATASHEETS\RESISTORS\PAN-ERJSER_NOV17.PDF
R14 R652 R660 R663 R785 R799 R803 R804 R807 R1243 R1277 R1278 = RESISTOR: RES 10K 1/16W 1% 0402; Chkd/date: VASANTHA/201216; Crtd /date: GEETHA/290506; Custom_Duty: 15%; Customs_HS_Code: 85332119; Distributor_name: DIGIKEY; Distributor_part_number: 311-10.0KLRTR-ND; Footprint Path: Y:\MIS_DATABASE\Library\ALTIUM_TOOL\PCB_FOOTPRINTS\Altium_Footprint_Lib.PcbLib; Height: 0.40MM; Library Path: Y:\MIS_DATABASE\Library\ALTIUM_TOOL\SCHEMATICS_PARTS\MS_DISCRETE_Library.schlib; Manufacturer: YAGEO AMERICA; Mfr_name: YAGEO AMERICA; Mfr_part_number: RC0402FR-0710KL; Mistral Part No: 110015090015-R; Package: 0402; Part_type: RESISTORS\FIXED; Project: VOCERA; RoHS: RoHS; Temperature: -55°C+155°C; Tolerance: 1%; Voltage: NA; Wattage: 1/16W; Weight: 0.65mg; Datasheet: Y:\MIS_DATABASE\DATASHEETS\RESISTORS\RCXXXXL-SER_MAR18.PDF
R198 = RESISTOR: RES 499E 1/16W 0.1% 0402; Chkd/date: ALVY/200921; Crtd /date: MANIRAJA/200921; Custom_Duty: 15%; Customs_HS_Code: 85332119; Distributor_name: DIGIKEY; Distributor_part_number: YAG1440CT-ND; Footprint Path: Y:\MIS_DATABASE\Library\ALTIUM_TOOL\PCB_FOOTPRINTS\Altium_Footprint_Lib.PcbLib; Height: 0.35MM; Library Path: Y:\MIS_DATABASE\Library\ALTIUM_TOOL\SCHEMATICS_PARTS\MS_DISCRETE_Library.schlib; Manufacturer: YAGEO AMERICA; Mfr_name: YAGEO AMERICA; Mfr_part_number: RT0402BRD07499RL; Mistral Part No: 110021020006-R; Package: 0402; Part_type: RESISTORS\FIXED; Project: TI_AM62x SKEVM_BRD; RoHS: RoHS; Temperature: -55°C+155°C; Tolerance: 0.1%; Voltage: NA; Wattage: 1/16W; Weight: 0.65mg; Datasheet: Y:\MIS_DATABASE\DATASHEETS\RESISTORS\YAGEO_RT-SERIES.PDF
R774 R775 R795 R796 = RESISTOR: RES 0E 1/10W JUMPER 0402; Assembly_Instruction: DNI; Chkd/date: VASANTHA/061216; Crtd /date: NAVEED/201014; Custom_Duty: 15%; Customs_HS_Code: 85332119; Distributor_name: DIGIKEY; Distributor_part_number: P0.0JCT-ND; Footprint Path: Y:\MIS_DATABASE\Library\ALTIUM_TOOL\PCB_FOOTPRINTS\Altium_Footprint_Lib.PcbLib; Height: 0.40MM; IBISSP_MODLES: VALUE REPEATING 2 TIME; Library Path: Y:\MIS_DATABASE\Library\ALTIUM_TOOL\SCHEMATICS_PARTS\MS_DISCRETE_Library.schlib; Manufacturer: PANASONIC-ECG; Mfr_name: PANASONIC-ECG; Mfr_part_number: ERJ-2GE0R00X; Mistral Part No: 110018030052-R; Package: 0402; Part_type: RESISTORS\FIXED; Project: AEGIS POM; RoHS: RoHS; Temperature: -55°C+155°C; Tolerance: NA; Voltage: NA; Wattage: 1/10W; Weight: 0.8mg; Datasheet: Y:\MIS_DATABASE\DATASHEETS\RESISTORS\PAN-ERJSER_NOV17.PDF
R790 = RESISTOR: RES 10K 1/16W 1% 0402; Assembly_Instruction: DNI; Chkd/date: VASANTHA/201216; Crtd /date: GEETHA/290506; Custom_Duty: 15%; Customs_HS_Code: 85332119; Distributor_name: DIGIKEY; Distributor_part_number: 311-10.0KLRTR-ND; Footprint Path: Y:\MIS_DATABASE\Library\ALTIUM_TOOL\PCB_FOOTPRINTS\Altium_Footprint_Lib.PcbLib; Height: 0.40MM; Library Path: Y:\MIS_DATABASE\Library\ALTIUM_TOOL\SCHEMATICS_PARTS\MS_DISCRETE_Library.schlib; Manufacturer: YAGEO AMERICA; Mfr_name: YAGEO AMERICA; Mfr_part_number: RC0402FR-0710KL; Mistral Part No: 110015090015-R; Package: 0402; Part_type: RESISTORS\FIXED; Project: VOCERA; RoHS: RoHS; Temperature: -55°C+155°C; Tolerance: 1%; Voltage: NA; Wattage: 1/16W; Weight: 0.65mg; Datasheet: Y:\MIS_DATABASE\DATASHEETS\RESISTORS\RCXXXXL-SER_MAR18.PDF
R806 = RESISTOR: RES 9.09K 1/16W 1% 0402; Chkd/date: VASANTHA/281216; Crtd /date: BAVISH/010611; Custom_Duty: 15%; Customs_HS_Code: 85332119; Distributor_name: DIGIKEY; Distributor_part_number: 541-9.09KLCT-ND; Footprint Path: Y:\MIS_DATABASE\Library\ALTIUM_TOOL\PCB_FOOTPRINTS\Altium_Footprint_Lib.PcbLib; Height: 0.40MM; Library Path: Y:\MIS_DATABASE\Library\ALTIUM_TOOL\SCHEMATICS_PARTS\MS_DISCRETE_Library.schlib; Manufacturer: VISHAY; Mfr_name: VISHAY; Mfr_part_number: CRCW04029K09FKED; Mistral Part No: 110011060006-R; Package: 0402; Part_type: RESISTORS\FIXED; Project: TE_MODULE; RoHS: RoHS; Temperature: -55°C+155°C; Tolerance: 1%; Voltage: NA; Wattage: 1/16W; Weight: 0.65mg; Datasheet: Y:\MIS_DATABASE\DATASHEETS\RESISTORS\CRCW0603.PDF
U3 = DIODE_ZENER_SOT23_13: DIODE ZENER 250mW 6.8V SOT23-123; Chkd/date: MANIRAJA/031017; Crtd /date: MANIRAJA/031017; Custom_Duty: 15%; Customs_HS_Code: 85412900; Distributor_name: DIGIKEY; Distributor_part_number: BZX84C6V8LT1GOSCT-ND; Height: 1.11MM; Manufacturer: ON SEMICONDUCTOR; Mfr_name: ON SEMICONDUCTOR; Mistral Part No: 130017100002-R; Package: SOT23-123; Part_type: DIODE\ZENER; Project: TI_MAXIE_CPB; RoHS: RoHS; Temperature: -65°C+150°C; Tolerance: NA; Voltage: 6.8V; Wattage: NA; Weight: 8mg; Datasheet: Y:\MIS_DATABASE\DATASHEETS\DISCRETES\DIODES\BZX84XX.PDF
U12 = TS3USB221ARSER_UQFN10: IC USB SWITCH 1:2 MUX/DEMUX UQFN10; Chkd/date: MAZHAR/110311; Crtd /date: BAVISH/250111; Custom_Duty: 15%; Customs_HS_Code: 85423100; Distributor_name: DIGIKEY; Distributor_part_number: 296-24019-1-ND; Footprint Path: Y:\MIS_DATABASE\Library\ALTIUM_TOOL\PCB_FOOTPRINTS\Altium_Footprint_Lib.PcbLib; Height: 0.60MM; Library Path: Y:\MIS_DATABASE\Library\ALTIUM_TOOL\SCHEMATICS_PARTS\MS_COMBINATIONAL_Library.schlib; Manufacturer: TEXAS INSTRUMENTS; Mfr_name: TEXAS INSTRUMENTS; Mistral Part No: 141011010030-R; Package: UQFN10; Part_type: ICS\DIGITAL\COMBINATIONAL; Project: PB BUG BASE; RoHS: RoHS; Temperature: -40°C+85°C; Tolerance: NA; Voltage: NA; Wattage: NA; Weight: NA; Datasheet: Y:\MIS_DATABASE\DATASHEETS\ICS\DIGITAL\COMBINATIONAL\TS3USB221ARSER.PDF
J37 = HEADER_3X1: CON HDR 1X3 2.00MM PITCH ST TH; Chkd/date: VASANTHA/04115; Crtd /date: VASANTHA/04115; Custom_Duty: 24%; Customs_HS_Code: 85369090; Distributor_name: DIGIKEY; Distributor_part_number: 952-1312-ND; Height: 5.25MM; Manufacturer: HARWIN INC; Mfr_name: HARWIN INC; Mfr_part_number: M22-2510305; Mistral Part No: 150015110010-R; Package: THRU-HOLE; Part_type: CONNECTOR\HEADERS; Project: ZK_BIOMETRIC; RoHS: RoHS; Temperature: -40°C+105°C; Tolerance: NA; Voltage: NA; Wattage: NA; Weight: NA; Datasheet: Y:\MIS_DATABASE\DATASHEETS\CONNECTORS\M22-251.PDF
SW16 = SW8_BD04: SWITCH DIP SPST 4POS ST SMD; Chkd/date: MANIRAJA/040619; Crtd /date: VASANTHA/241221; Custom_Duty: 24%; Customs_HS_Code: 85369090; Distributor_name: DIGIKEY; Distributor_part_number: CT3110CT-ND; Footprint Path: Y:\MIS_DATABASE\Library\ALTIUM_TOOL\PCB_FOOTPRINTS\Altium_Footprint_Lib.PcbLib; Height: 2.65MM; Library Path: Y:\MIS_DATABASE\Library\ALTIUM_TOOL\SCHEMATICS_PARTS\MS_SWITCH_Library.schlib; Mfr_name: CTS; Mfr_part_number: 218-4LPSTR; Mistral Part No: 130014120039-R; Package: SMD; Part_type: ELECTRO-MECHANICAL\SWITCH; Project: FREE SCALE POM; RoHS: RoHS; Temperature: -55°C+85°C; Tolerance: NA; Voltage: NA; Wattage: NA; Weight: NA; Datasheet: Y:\MIS_DATABASE\DATASHEETS\MISC\SWITCHES\128-XXLPST.PDF
U268 = SN74CBTLV3257D_SOIC16: IC 4BIT 1-OF-2 FET MULTIPLEXER/DEMULTIPLEXER TSSOP16; Chkd/date: MANIRAJA/290419; Crtd /date: ALVY/290419; Custom_Duty: 15%; Customs_HS_Code: 85423100; Distributor_name: DIGIKEY; Distributor_part_number: 296-23728-1-ND; Footprint Path: Y:\MIS_DATABASE\Library\ALTIUM_TOOL\PCB_FOOTPRINTS\Altium_Footprint_Lib.PcbLib; Height: 1.20MM; Library Path: Y:\MIS_DATABASE\Library\ALTIUM_TOOL\SCHEMATICS_PARTS\MS_COMBINATIONAL_Library.schlib; Manufacturer: TEXAS INSTRUMENTS; Mfr_name: TEXAS INSTRUMENTS; Mistral Part No: 141019040004-R; Package: TSSOP16; Part_type: ICS\DIGITAL\COMBINATIONAL; Project: J7ES_SOM_DUAL-LEO_PMIC; RoHS: RoHS; Temperature: -55°C+125°C; Tolerance: NA; Voltage: NA; Wattage: NA; Weight: 62mg; Datasheet: Y:\MIS_DATABASE\DATASHEETS\ICS\DIGITAL\COMBINATIONAL\SN74CBTLV3257-EP.PDF

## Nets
DGND: C35.2 C216.2 C585.2 C768.2 C899.2 C965.2 C970.2 C992.2 C1014.2 C1019.2 C1027.2 C1205.2 D36.2(ANODE) J37.2 R14.1 R198.2 R222.2 R249.2 R256.2 R652.1 R660.1 R663.1 R790.2 R799.2 R803.2 R804.2 R807.2 R949.2 R951.2 R953.2 R1100.2 R1243.2 U3.1(A) U12.5(GND) U47.8(GND) U177.8(GND) U206.8(GND) U268.8(GND) ; also on sheet 11 12 13 14 15 16 17 18 20 21 25 26 27 28 29 30 31 32 33 34 35 36 37 38 39 40 41 42 43 44 45 46 47 48 49 50 51 52 53 54 55 56 57 58 59 60 61 62 63 64 65 66 67 68 69 70 71 72 73 76 77 78 79 81 82 83 84
VBUS_USBC_CONN: R9.1 ; also on sheet 53
VCC3V3_XDS: R952.1 ; also on sheet 47
VCCA_3V3: R1277.2 R1278.2 ; also on sheet 54 69 70 71 72 75 81
VDD_CPU_AVS: C992.1 U59.L25(VMON2_IR_VCPU) ; also on sheet 27 28 54 70 74
ATEST0: TP149.1(TP) U59.M30(RSVD)
ATEST1: TP144.1(TP) U59.J29(RSVD)
EVM_PDN_TEST: R663.2 SW16.3 U268.1(S)
EVM_PMIC_EN: R652.2 SW16.1 U268.11(3B1)
EVM_SVS_EN: R660.2 SW16.2 U268.14(4B1)
EXT_I2C_SCL: J37.1 R1277.1 U268.2(1B1)
EXT_I2C_SDA: J37.3 R1278.1 U268.5(2B1)
EXT_MIPI_EMU0: U47.11(3B1) ; also on sheet 48
EXT_MIPI_EMU1: U47.14(4B1) ; also on sheet 48
EXT_MIPI_TCK: U47.2(1B1) ; also on sheet 48
EXT_MIPI_TDI: U206.5(2B1) ; also on sheet 48
EXT_MIPI_TDO: U206.2(1B1) ; also on sheet 48
EXT_MIPI_TMS: U206.11(3B1) ; also on sheet 48
EXT_MIPI_TRST#: U47.5(2B1) ; also on sheet 48
H_WKUP_I2C0_SCL: U268.4(1A) ; also on sheet 54 69 70 71
H_WKUP_I2C0_SDA: U268.7(2A) ; also on sheet 54 69 70 71
IFORCE: TP161.1(TP) U59.L30(RSVD)
JTAG_MUX1_OE#: C772.2 R951.1 U206.15(~{OE})
JTAG_MUX2_OE#: C204.2 R256.1 U47.15(~{OE})
JTAG_MUX_SEL: R952.2 R953.1 U47.1(S) U206.1(S) ; also on sheet 48
LJCB_ATEST0: TP275.1(TP) U59.AH7(RSVD)
LJCB_ATEST1: TP269.1(TP) U59.AH8(RSVD)
MAIN_ATEST: TP160.1(TP) U59.L28(RSVD)
MON1_ER_VSYS: C1019.1 R1100.1 R1105.2 U59.G26(VMON1_ER_VSYS)
MON3_IR_VEXT1V8: C1027.1 R1097.2 U59.K30(VMON3_IR_VEXT1P8)
MON4_IR_VEXT1V8: C970.1 R1050.2 U59.M26(VMON4_IR_VEXT1P8)
MON5_IR_VEXT1V8: C965.1 R1046.2 U59.M29(VMON5_IR_VEXT3P3)
MUX_USB0_DATA_N: R56.1 U12.7(D-)
MUX_USB0_DATA_P: R57.1 U12.8(D+)
PMIC_ENABLE: U268.9(3A) ; also on sheet 69
PMIC_WDOG_DISABLE: SW16.4 ; also on sheet 69
R_MUX_USB0_DATA_N: R775.1 R796.1
R_MUX_USB0_DATA_P: R774.1 R795.1
R_USB0_DATA_N: R29.2 U12.2(1D-)
R_USB0_DATA_P: R30.2 U12.1(1D+)
SOC_EMU0: R241.2 SW4.1 TP78.1(TP) U47.9(3A) U59.F19(EMU0)
SOC_EMU1: R232.2 SW4.2 TP72.1(TP) U47.12(4A) U59.E17(EMU1)
SOC_TCK: TP82.1(TP) U47.4(1A) U59.F21(TCK)
SOC_TDI: TP69.1(TP) U59.V33(TDI) U206.7(2A)
SOC_TDO: TP71.1(TP) U59.W33(TDO) U206.4(1A)
SOC_TMS: TP68.1(TP) U59.V32(TMS) U206.9(3A)
SOC_TRST#: TP84.1(TP) U47.7(2A) U59.F17(TRSTN)
SOC_WKUP_I2C0_SCL: U268.3(1B2) ; also on sheet 18 43
SOC_WKUP_I2C0_SDA: U268.6(2B2) ; also on sheet 18 43
SVS_ENABLE: U268.12(4A) ; also on sheet 54
SYS_MCU_EN: U268.10(3B2) U268.13(4B2) ; also on sheet 35
TEMP_DIODE_P0: TP162.1(TP) U59.E28(RSVD)
TEMP_DIODE_P1: TP132.1(TP) U59.F27(RSVD)
USB0_D_N: R56.2 R796.2 U59.AH16(USB0_DM)
USB0_D_P: R57.2 R795.2 U59.AH17(USB0_DP)
USB0_DATA_N: R29.1 R775.2 ; also on sheet 53
USB0_DATA_P: R30.1 R774.2 ; also on sheet 53
USB0_DRVVBUS: R803.1 U177.11(3B1) ; also on sheet 53
USB0_DRVVBUS_MUX: U177.9(3A) ; also on sheet 20
USB0_ID: U177.2(1B1) ; also on sheet 53
USB0_ID_MUX: U59.AH20(USB0_ID) U177.4(1A)
USB0_RCALIB: R198.1 U59.AH22(USB0_RCALIB)
USB0_VBUS_MUX: U59.AG19(USB0_VBUS) U177.7(2A)
USB0_VBUS_SOC: R13.2 R14.2 U177.5(2B1)
USB1_DRVVBUS: R806.1 R807.1 U177.10(3B2) ; also on sheet 51
USB1_HUB_D_N: U12.4(2D-) ; also on sheet 51
USB1_HUB_D_P: U12.3(2D+) ; also on sheet 51
USB1_ID: U177.3(1B2) ; also on sheet 51
USB1_VBUS_SOC: R804.1 R806.2 U177.6(2B2)
USB2.0_MUX_OEn: R799.1 U12.6(~{OE}) U177.12(4A) U177.15(~{OE})
USB2.0_MUX_SEL: R785.2 R790.1 U12.9(S) U177.1(S) ; also on sheet 38
VEXT_1V8_RAIL_MON3: R1097.1 TP318.1(TP)
VEXT_1V8_RAIL_MON4: R1050.1 TP312.1(TP)
VEXT_3V3_RAIL_MON5: R1046.1 TP313.1(TP)
VPP_CORE_1V8: C899.1 R1016.1 TP122.1(TP) U59.V29(VPP_CORE)
VPP_EFUSE_1V8: R1016.2 R1090.1 ; also on sheet 72
VPP_MCU_1V8: C1014.1 R1090.2 TP155.1(TP) U59.F26(VPP_MCU)
VSENSE: TP163.1(TP) U59.L29(RSVD)
VSYS_3V3: C1205.1 R444.1 R653.2 R661.2 R664.2 R1105.1 U268.16(VCC) ; also on sheet 35 36 40 47 49 62 63 65 66 67 68 69 73 75 76 77 78 79
VSYS_IO_3V3: C35.1 C585.1 C768.1 C772.1 R785.1 U12.10(VCC) U177.16(VCC) U206.16(VCC) ; also on sheet 18 20 29 30 31 32 33 35 36 37 38 40 41 42 43 45 46 48 50 51 53 56 57 58 59 60 61 65 66 68 75 81 82
VSYS_MCUIO_3V3: C204.1 C216.1 R232.1 R241.1 R673.2 U47.16(VCC) ; also on sheet 16 17 18 21 35 36 43 44 48 49 55 62 65 68 75
XDS110_EMU0: U47.10(3B2) ; also on sheet 47
XDS110_EMU1: U47.13(4B2) ; also on sheet 47
XDS110_TCK: U47.3(1B2) ; also on sheet 47
XDS110_TDI: U206.6(2B2) ; also on sheet 47
XDS110_TDO: U206.3(1B2) ; also on sheet 47
XDS110_TMS: U206.10(3B2) ; also on sheet 47
XDS110_TRST#: U47.6(2B2) ; also on sheet 47
N16860253: R9.2 R13.1 U3.3(C)
N33033037: R949.1 U206.12(4A)
N33104471: R1243.1 U268.15(~{OE})
N34899945: R440.1 R444.2
N34899947: D36.1(CATHODE) R440.2
N37512355: R653.1 SW16.8
N37512529: R661.1 SW16.7
N37513072: R664.1 SW16.6
N37514843: R673.1 SW16.5
N39003104: R249.1 SW4.4
N39003106: R222.1 SW4.3

Not connected (* = marked no-connect by the designer): U3 2(NC)*; U177 13(4B2)* 14(4B1)*; U206 13(4B2)* 14(4B1)*

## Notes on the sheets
sheet 22
- SPECIAL, DEBUG & RSVD
- Vth(min) = 0.45V
- If monitoring VSYS_3V3,
  protect SoC from
  1st stage fault.
  Alternatively, monitoring
  protected VCCA_3V3
  requires no Zener diode.
- JTAG AND TRACE MUX
- NOTE:SW4.1&2-OFF
  (Default wait-in-reset disabled)
- JTAG - 1:2  MUX : Truth Table
- MUX_SEL
- CONDITION
- FUNCTION
- External Emulator attached &
  No Power to XDS110
- LOW
- A-->B1 port [EXTERNAL EMU]
- (default)
- No External Emulator attached &
  XDS110 Powered via USB
- HIGH
- A-->B2 port [ON Board EMU]
- LOW
- External Emulator attached &
  XDS110 Powered via USB
- A-->B1 port [EXTERNAL EMU]
- No External Emulator attached &
  No Power to XDS110
- LOW
- A-->B1 port [EXTERNAL EMU]
sheet 23
- EVM PMIC Support Circuitry
- EVM development & evaluation Test circuitry
- (TI EVM Only)
- (EVM Bd Setting & Leo NVM Default):
- SW16
- Function
- -1 = Closed (High)
- Enable the PMIC by overriding SYS_MCU_ENABLE
- OEn
- S
- Bit State
- = Open (Low)
- Enble the PMIC from SYS_MCU_EN
- 0
- 0
- A = B1
- -2 = Closed (High)
- ENABLE  SVS EN from SW16.2
- 0
- 1
- A = B2
- = Open (Low)
- ENABLE SVS EN FROM SYS_MCU_EN
- 1
- X
- Open
- -3 = Closed (High)
- 1. PMIC EN from SYS_MCU_EN
- 2. On Board WKUP I2C0 is selected
- 3. SVS_EN is controlled from SYS_MCU_EN
- = Open (Low)
- 1. PMIC_EN is controlled from SW16.1
- 2. EXT_I2C is selected
- 3. SVS_EN is controlled from SW16.2
- -4 = Closed (High)
- = Open (Low)
- Disable WDOG Timer
- Enable WDOG Timer
sheet 24
- USB0 2.0
- By Pass
  USB MUX
- Mount - R796,R795,R774,R775
  DNI   -R57,R56,R30,R29
- USB MUX
  (Default)
- Mount -R57,R56,R30,R29
  DNI   - R796,R795,R774,R775
- USB0 2.0
- TYPE-C
- Note: Option to by passive Mux.
- Note: Option to by passive Mux.
- USB2.0 MUX
- SEL
- OUTPUT
- LOW
- A to B1 (USBC) Default
- USB HUB
- HIGH
- A to B2 (USB HUB)
- USB VBUS Resistor divider circuit
- Note: Recommended VBUS circuit for USB connector. Supports 5V-30V VBUS
- Note: Recommended VBUS circuit for embedded Hub
